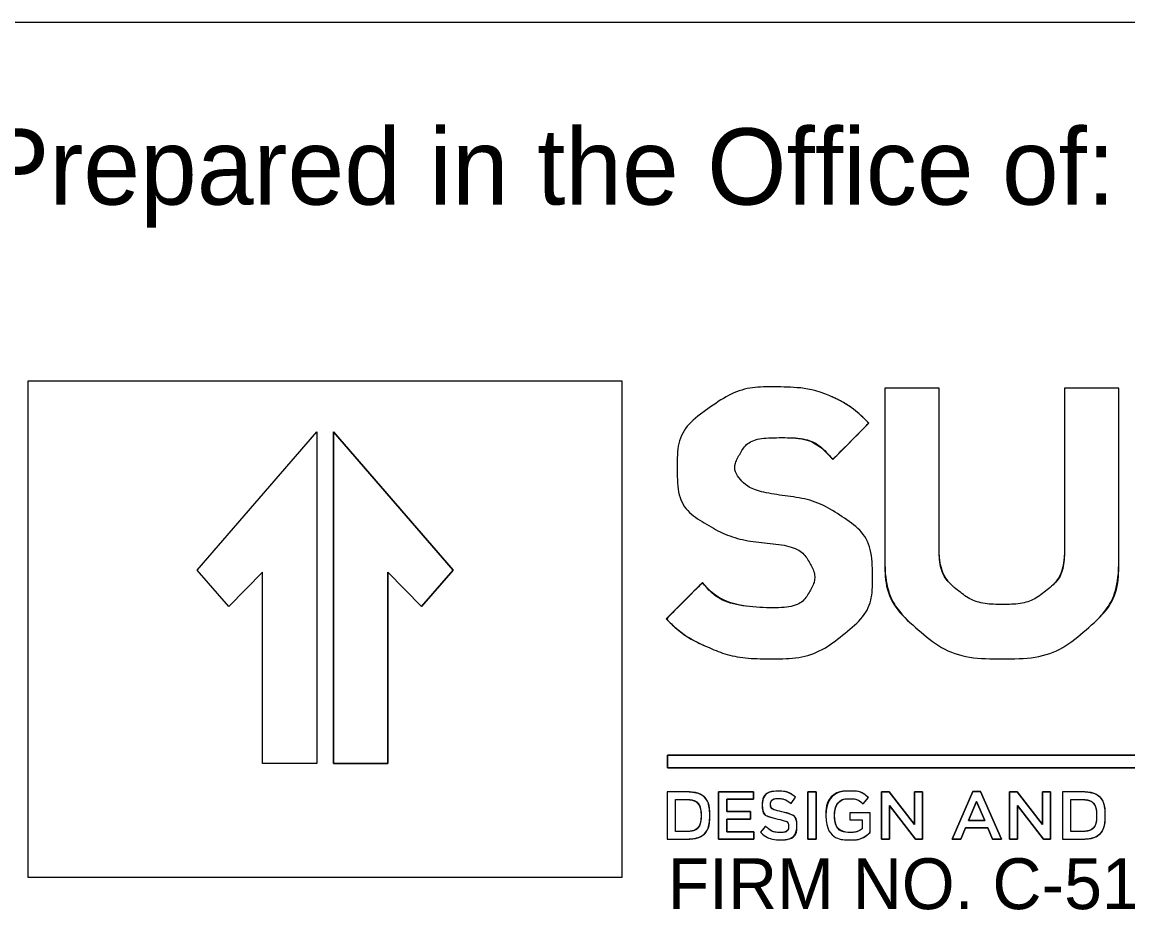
# Model space of a CAD drawing. Extents: x 1359317 to 1361345, y 1001522 to 1002524.
# Drawn here: x 1359513.4 to 1359573.9, y 1001664.8 to 1001713.3 of the extents above; entities that cross this region are included whole.
import ezdxf

# ---------------------------------------------------------------- set-up
doc = ezdxf.new("R2010")
doc.units = 0
doc.layers.add('Old_Level_3', color=7, linetype='Continuous')
doc.layers.add('Sheet Title CELL', color=7, linetype='Continuous')

msp = doc.modelspace()

# ---------------------------------------------------------------- linework, layer by layer
at = {"layer": 'Old_Level_3'}
for p, q in [((1359557.722, 1001689.42), (1359559.699, 1001691.4)), ((1359550.603, 1001682.684), (1359548.625, 1001680.703)), ((1359553.873, 1001670.535), (1359553.873, 1001670.527)), ((1359554.326, 1001670.568), (1359554.326, 1001670.575)), ((1359555.446, 1001670.616), (1359555.689, 1001670.959)), ((1359559.387, 1001670.598), (1359559.674, 1001670.941)), ((1359550.525, 1001669.955), (1359550.525, 1001669.948)), ((1359551.001, 1001669.955), (1359551.001, 1001669.963)), ((1359557.353, 1001669.955), (1359557.353, 1001669.948)), ((1359557.828, 1001669.955), (1359557.828, 1001669.963)), ((1359572.156, 1001669.955), (1359572.156, 1001669.948)), ((1359572.631, 1001669.955), (1359572.631, 1001669.963)), ((1359554.042, 1001669.365), (1359553.77, 1001669.04)), ((1359555.313, 1001669.361), (1359555.313, 1001669.354)), ((1359555.766, 1001669.398), (1359555.766, 1001669.406))]:
    msp.add_line(p, q, dxfattribs=at)
for points in [[(1359546.211, 1001693.693), (1359513.702, 1001693.693), (1359513.702, 1001666.583), (1359546.211, 1001666.583), (1359546.211, 1001693.693)], [(1359546.211, 1001693.693), (1359513.702, 1001693.693), (1359513.702, 1001666.583), (1359546.211, 1001666.583), (1359546.211, 1001693.693)], [(1359563.543, 1001684.765), (1359563.543, 1001693.322), (1359560.571, 1001693.322), (1359560.571, 1001683.972)], [(1359573.374, 1001683.972), (1359573.374, 1001693.322), (1359570.402, 1001693.322), (1359570.402, 1001684.765)], [(1359529.517, 1001690.92), (1359529.517, 1001672.793), (1359526.545, 1001672.793), (1359526.545, 1001683.249), (1359524.704, 1001681.377), (1359522.973, 1001683.363), (1359529.517, 1001690.92)], [(1359529.517, 1001690.92), (1359529.517, 1001672.793), (1359526.545, 1001672.793), (1359526.545, 1001683.249), (1359524.704, 1001681.377), (1359522.973, 1001683.363), (1359529.517, 1001690.92)], [(1359536.975, 1001683.363), (1359535.244, 1001681.377), (1359533.403, 1001683.249), (1359533.403, 1001672.793), (1359530.431, 1001672.793), (1359530.431, 1001690.92), (1359536.975, 1001683.363)], [(1359620.7, 1001672.564), (1359548.682, 1001672.564), (1359548.682, 1001673.251), (1359620.7, 1001673.251), (1359620.7, 1001672.564)], [(1359620.7, 1001673.251), (1359548.682, 1001673.251), (1359548.682, 1001672.564), (1359620.7, 1001672.564), (1359620.7, 1001673.251)], [(1359549.63, 1001671.247), (1359548.669, 1001671.247), (1359548.669, 1001668.664), (1359549.63, 1001668.664)], [(1359551.475, 1001671.247), (1359553.387, 1001671.247), (1359553.387, 1001670.841), (1359551.928, 1001670.841), (1359551.928, 1001670.169), (1359553.221, 1001670.169), (1359553.221, 1001669.763), (1359551.928, 1001669.763), (1359551.928, 1001669.07), (1359553.405, 1001669.07), (1359553.405, 1001668.664), (1359551.475, 1001668.664), (1359551.475, 1001671.247)], [(1359551.475, 1001668.664), (1359553.405, 1001668.664), (1359553.405, 1001669.07), (1359551.928, 1001669.07), (1359551.928, 1001669.763), (1359553.221, 1001669.763), (1359553.221, 1001670.169), (1359551.928, 1001670.169), (1359551.928, 1001670.841), (1359553.387, 1001670.841), (1359553.387, 1001671.247), (1359551.475, 1001671.247), (1359551.475, 1001668.664)], [(1359556.362, 1001671.247), (1359556.816, 1001671.247), (1359556.816, 1001668.664), (1359556.362, 1001668.664), (1359556.362, 1001671.247)], [(1359556.362, 1001668.664), (1359556.816, 1001668.664), (1359556.816, 1001671.247), (1359556.362, 1001671.247), (1359556.362, 1001668.664)], [(1359560.392, 1001671.247), (1359560.811, 1001671.247), (1359562.193, 1001669.461), (1359562.193, 1001671.247), (1359562.639, 1001671.247), (1359562.639, 1001668.664), (1359562.259, 1001668.664), (1359560.837, 1001670.502), (1359560.837, 1001668.664), (1359560.392, 1001668.664), (1359560.392, 1001671.247)], [(1359560.392, 1001668.664), (1359560.837, 1001668.664), (1359560.837, 1001670.502), (1359562.259, 1001668.664), (1359562.639, 1001668.664), (1359562.639, 1001671.247), (1359562.193, 1001671.247), (1359562.193, 1001669.461), (1359560.811, 1001671.247), (1359560.392, 1001671.247), (1359560.392, 1001668.664)], [(1359565.393, 1001671.265), (1359565.814, 1001671.265), (1359566.948, 1001668.664), (1359566.469, 1001668.664), (1359566.207, 1001669.287), (1359564.988, 1001669.287), (1359564.723, 1001668.664), (1359564.259, 1001668.664), (1359565.393, 1001671.265)], [(1359564.259, 1001668.664), (1359564.723, 1001668.664), (1359564.988, 1001669.287), (1359566.207, 1001669.287), (1359566.469, 1001668.664), (1359566.948, 1001668.664), (1359565.814, 1001671.265), (1359565.393, 1001671.265), (1359564.259, 1001668.664)], [(1359567.389, 1001671.247), (1359567.81, 1001671.247), (1359569.191, 1001669.461), (1359569.191, 1001671.247), (1359569.637, 1001671.247), (1359569.637, 1001668.664), (1359569.257, 1001668.664), (1359567.835, 1001670.502), (1359567.835, 1001668.664), (1359567.389, 1001668.664), (1359567.389, 1001671.247)], [(1359567.389, 1001668.664), (1359567.835, 1001668.664), (1359567.835, 1001670.502), (1359569.257, 1001668.664), (1359569.637, 1001668.664), (1359569.637, 1001671.247), (1359569.191, 1001671.247), (1359569.191, 1001669.461), (1359567.81, 1001671.247), (1359567.389, 1001671.247), (1359567.389, 1001668.664)], [(1359571.261, 1001671.247), (1359570.299, 1001671.247), (1359570.299, 1001668.664), (1359571.261, 1001668.664)], [(1359549.63, 1001669.077), (1359549.122, 1001669.077), (1359549.122, 1001670.834), (1359549.63, 1001670.834)], [(1359566.042, 1001669.69), (1359565.596, 1001670.723), (1359565.154, 1001669.69), (1359566.042, 1001669.69)], [(1359565.154, 1001669.69), (1359565.596, 1001670.723), (1359566.042, 1001669.69), (1359565.154, 1001669.69)], [(1359571.261, 1001669.077), (1359570.753, 1001669.077), (1359570.753, 1001670.834), (1359571.261, 1001670.834)], [(1359559.766, 1001669.022), (1359559.766, 1001670.107), (1359558.668, 1001670.107), (1359558.668, 1001669.712), (1359559.328, 1001669.712), (1359559.328, 1001669.228)]]:
    msp.add_lwpolyline(points, dxfattribs=at)
msp.add_lwpolyline([(1359530.431, 1001690.92), (1359530.431, 1001672.793), (1359533.403, 1001672.793), (1359533.403, 1001683.249), (1359535.244, 1001681.377), (1359536.975, 1001683.363)], close=True, dxfattribs=at)
for points, degree in [([(1359557.573, 1001692.886), (1359558.331, 1001692.557), (1359559.04, 1001692.061), (1359559.699, 1001691.4), (1359559.699, 1001691.4), (1359557.722, 1001689.42), (1359557.722, 1001689.42), (1359557.062, 1001690.212), (1359556.14, 1001690.609), (1359554.952, 1001690.609), (1359553.767, 1001690.609), (1359553.008, 1001690.328), (1359552.678, 1001689.766), (1359552.349, 1001689.205), (1359552.349, 1001688.727), (1359552.678, 1001688.331), (1359553.008, 1001687.934), (1359553.767, 1001687.637), (1359554.952, 1001687.439), (1359556.205, 1001687.307), (1359557.343, 1001686.894), (1359558.365, 1001686.201), (1359559.386, 1001685.508), (1359559.896, 1001684.402), (1359559.896, 1001682.883), (1359559.896, 1001681.693), (1359559.352, 1001680.67), (1359558.261, 1001679.812), (1359557.17, 1001678.954), (1359555.899, 1001678.524), (1359554.448, 1001678.524), (1359553.071, 1001678.524), (1359551.921, 1001678.722), (1359550.997, 1001679.118), (1359550.074, 1001679.515), (1359549.284, 1001680.043), (1359548.625, 1001680.703), (1359548.625, 1001680.703), (1359550.603, 1001682.684), (1359550.603, 1001682.684), (1359551.262, 1001681.892), (1359552.383, 1001681.43), (1359553.964, 1001681.298), (1359555.283, 1001681.298), (1359556.105, 1001681.579), (1359556.432, 1001682.14), (1359556.758, 1001682.701), (1359556.758, 1001683.262), (1359556.432, 1001683.824), (1359556.105, 1001684.385), (1359555.283, 1001684.731), (1359553.964, 1001684.863), (1359552.778, 1001684.995), (1359551.69, 1001685.359), (1359550.701, 1001685.953), (1359549.713, 1001686.548), (1359549.217, 1001687.571), (1359549.217, 1001689.024), (1359549.217, 1001690.337), (1359549.78, 1001691.392), (1359550.904, 1001692.188), (1359552.028, 1001692.985), (1359553.183, 1001693.382), (1359554.369, 1001693.382), (1359555.747, 1001693.382), (1359556.815, 1001693.218), (1359557.573, 1001692.886)], 3), ([(1359557.573, 1001692.886), (1359556.815, 1001693.218), (1359555.747, 1001693.382), (1359554.369, 1001693.382), (1359553.183, 1001693.382), (1359552.028, 1001692.985), (1359550.904, 1001692.188), (1359549.78, 1001691.392), (1359549.217, 1001690.337), (1359549.217, 1001689.024), (1359549.217, 1001687.571), (1359549.713, 1001686.548), (1359550.701, 1001685.953), (1359551.69, 1001685.359), (1359552.778, 1001684.995), (1359553.964, 1001684.863), (1359555.283, 1001684.731), (1359556.105, 1001684.385), (1359556.432, 1001683.824), (1359556.758, 1001683.262), (1359556.758, 1001682.701), (1359556.432, 1001682.14), (1359556.105, 1001681.579), (1359555.283, 1001681.298), (1359553.964, 1001681.298), (1359552.383, 1001681.43), (1359551.262, 1001681.892), (1359550.603, 1001682.684)], 3), ([(1359559.699, 1001691.4), (1359559.04, 1001692.061), (1359558.331, 1001692.557), (1359557.573, 1001692.886)], 2), ([(1359563.543, 1001693.322), (1359563.543, 1001693.322), (1359563.543, 1001684.765), (1359563.543, 1001684.765), (1359563.543, 1001683.642), (1359563.88, 1001682.817), (1359564.539, 1001682.288), (1359565.199, 1001681.76), (1359566.026, 1001681.496), (1359567.015, 1001681.496), (1359568.004, 1001681.496), (1359568.791, 1001681.76), (1359569.45, 1001682.288), (1359570.109, 1001682.817), (1359570.402, 1001683.642), (1359570.402, 1001684.765), (1359570.402, 1001684.765), (1359570.402, 1001693.322), (1359570.402, 1001693.322), (1359570.402, 1001693.322), (1359573.374, 1001693.322), (1359573.374, 1001693.322), (1359573.374, 1001693.322), (1359573.374, 1001683.972), (1359573.374, 1001683.972), (1359573.374, 1001682.453), (1359572.8, 1001681.166), (1359571.58, 1001680.109), (1359570.361, 1001679.053), (1359568.847, 1001678.524), (1359567.001, 1001678.524), (1359565.155, 1001678.524), (1359563.62, 1001679.053), (1359562.402, 1001680.109), (1359561.181, 1001681.166), (1359560.571, 1001682.453), (1359560.571, 1001683.972), (1359560.571, 1001683.972), (1359560.571, 1001693.322), (1359560.571, 1001693.322), (1359560.571, 1001693.322), (1359563.543, 1001693.322), (1359563.543, 1001693.322)], 3), ([(1359548.625, 1001680.703), (1359549.284, 1001680.043), (1359550.074, 1001679.515), (1359550.997, 1001679.118), (1359551.921, 1001678.722), (1359553.071, 1001678.524), (1359554.448, 1001678.524), (1359555.899, 1001678.524), (1359557.17, 1001678.954), (1359558.261, 1001679.812), (1359559.352, 1001680.67), (1359559.896, 1001681.693), (1359559.896, 1001682.883), (1359559.896, 1001684.402), (1359559.386, 1001685.508), (1359558.365, 1001686.201), (1359557.343, 1001686.894), (1359556.205, 1001687.307), (1359554.952, 1001687.439), (1359553.767, 1001687.637), (1359553.008, 1001687.934), (1359552.678, 1001688.331), (1359552.349, 1001688.727), (1359552.349, 1001689.205), (1359552.678, 1001689.766), (1359553.008, 1001690.328), (1359553.767, 1001690.609), (1359554.952, 1001690.609), (1359556.14, 1001690.609), (1359557.062, 1001690.212), (1359557.722, 1001689.42)], 3), ([(1359570.402, 1001684.765), (1359570.402, 1001683.642), (1359570.109, 1001682.817), (1359569.45, 1001682.288), (1359568.791, 1001681.76), (1359568.004, 1001681.496), (1359567.015, 1001681.496), (1359566.026, 1001681.496), (1359565.199, 1001681.76), (1359564.539, 1001682.288), (1359563.88, 1001682.817), (1359563.543, 1001683.642), (1359563.543, 1001684.765)], 3), ([(1359560.571, 1001683.972), (1359560.571, 1001682.453), (1359561.181, 1001681.166), (1359562.402, 1001680.109), (1359563.62, 1001679.053), (1359565.155, 1001678.524), (1359567.001, 1001678.524), (1359568.847, 1001678.524), (1359570.361, 1001679.053), (1359571.58, 1001680.109), (1359572.8, 1001681.166), (1359573.374, 1001682.453), (1359573.374, 1001683.972)], 3), ([(1359548.669, 1001671.247), (1359548.669, 1001671.247), (1359549.63, 1001671.247), (1359549.63, 1001671.247), (1359550.441, 1001671.247), (1359551.001, 1001670.69), (1359551.001, 1001669.963), (1359551.001, 1001669.963), (1359551.001, 1001669.955), (1359551.001, 1001669.955), (1359551.001, 1001669.228), (1359550.441, 1001668.664), (1359549.63, 1001668.664), (1359549.63, 1001668.664), (1359548.669, 1001668.664), (1359548.669, 1001668.664), (1359548.669, 1001668.664), (1359548.669, 1001671.247), (1359548.669, 1001671.247)], 3), ([(1359551.001, 1001669.963), (1359551.001, 1001670.69), (1359550.441, 1001671.247), (1359549.63, 1001671.247)], 2), ([(1359553.77, 1001669.04), (1359553.77, 1001669.04), (1359554.042, 1001669.365), (1359554.042, 1001669.365), (1359554.289, 1001669.151), (1359554.539, 1001669.029), (1359554.857, 1001669.029), (1359555.136, 1001669.029), (1359555.313, 1001669.162), (1359555.313, 1001669.354), (1359555.313, 1001669.354), (1359555.313, 1001669.361), (1359555.313, 1001669.361), (1359555.313, 1001669.546), (1359555.21, 1001669.645), (1359554.731, 1001669.756), (1359554.182, 1001669.889), (1359553.873, 1001670.051), (1359553.873, 1001670.527), (1359553.873, 1001670.527), (1359553.873, 1001670.535), (1359553.873, 1001670.535), (1359553.873, 1001670.978), (1359554.241, 1001671.284), (1359554.753, 1001671.284), (1359555.129, 1001671.284), (1359555.427, 1001671.17), (1359555.689, 1001670.959), (1359555.689, 1001670.959), (1359555.446, 1001670.616), (1359555.446, 1001670.616), (1359555.214, 1001670.789), (1359554.982, 1001670.882), (1359554.746, 1001670.882), (1359554.481, 1001670.882), (1359554.326, 1001670.745), (1359554.326, 1001670.575), (1359554.326, 1001670.575), (1359554.326, 1001670.568), (1359554.326, 1001670.568), (1359554.326, 1001670.369), (1359554.444, 1001670.28), (1359554.941, 1001670.162), (1359555.486, 1001670.029), (1359555.766, 1001669.834), (1359555.766, 1001669.406), (1359555.766, 1001669.406), (1359555.766, 1001669.398), (1359555.766, 1001669.398), (1359555.766, 1001668.915), (1359555.387, 1001668.627), (1359554.845, 1001668.627), (1359554.451, 1001668.627), (1359554.079, 1001668.763), (1359553.77, 1001669.04)], 3), ([(1359555.689, 1001670.959), (1359555.427, 1001671.17), (1359555.129, 1001671.284), (1359554.753, 1001671.284), (1359554.241, 1001671.284), (1359553.873, 1001670.978), (1359553.873, 1001670.535)], 3), ([(1359557.353, 1001669.948), (1359557.353, 1001669.948), (1359557.353, 1001669.955), (1359557.353, 1001669.955), (1359557.353, 1001670.679), (1359557.906, 1001671.291), (1359558.683, 1001671.291), (1359559.132, 1001671.291), (1359559.409, 1001671.166), (1359559.674, 1001670.941), (1359559.674, 1001670.941), (1359559.387, 1001670.598), (1359559.387, 1001670.598), (1359559.187, 1001670.767), (1359558.993, 1001670.874), (1359558.665, 1001670.874), (1359558.189, 1001670.874), (1359557.828, 1001670.457), (1359557.828, 1001669.963), (1359557.828, 1001669.963), (1359557.828, 1001669.955), (1359557.828, 1001669.955), (1359557.828, 1001669.424), (1359558.178, 1001669.033), (1359558.705, 1001669.033), (1359558.948, 1001669.033), (1359559.169, 1001669.11), (1359559.328, 1001669.228), (1359559.328, 1001669.228), (1359559.328, 1001669.712), (1359559.328, 1001669.712), (1359559.328, 1001669.712), (1359558.668, 1001669.712), (1359558.668, 1001669.712), (1359558.668, 1001669.712), (1359558.668, 1001670.107), (1359558.668, 1001670.107), (1359558.668, 1001670.107), (1359559.766, 1001670.107), (1359559.766, 1001670.107), (1359559.766, 1001670.107), (1359559.766, 1001669.022), (1359559.766, 1001669.022), (1359559.512, 1001668.804), (1359559.147, 1001668.619), (1359558.69, 1001668.619), (1359557.884, 1001668.619), (1359557.353, 1001669.195), (1359557.353, 1001669.948)], 3), ([(1359559.674, 1001670.941), (1359559.409, 1001671.166), (1359559.132, 1001671.291), (1359558.683, 1001671.291), (1359557.906, 1001671.291), (1359557.353, 1001670.679), (1359557.353, 1001669.955)], 3), ([(1359570.299, 1001671.247), (1359570.299, 1001671.247), (1359571.261, 1001671.247), (1359571.261, 1001671.247), (1359572.071, 1001671.247), (1359572.631, 1001670.69), (1359572.631, 1001669.963), (1359572.631, 1001669.963), (1359572.631, 1001669.955), (1359572.631, 1001669.955), (1359572.631, 1001669.228), (1359572.071, 1001668.664), (1359571.261, 1001668.664), (1359571.261, 1001668.664), (1359570.299, 1001668.664), (1359570.299, 1001668.664), (1359570.299, 1001668.664), (1359570.299, 1001671.247), (1359570.299, 1001671.247)], 3), ([(1359572.631, 1001669.963), (1359572.631, 1001670.69), (1359572.071, 1001671.247), (1359571.261, 1001671.247)], 2), ([(1359549.122, 1001670.834), (1359549.122, 1001670.834), (1359549.122, 1001669.077), (1359549.122, 1001669.077), (1359549.122, 1001669.077), (1359549.63, 1001669.077), (1359549.63, 1001669.077), (1359550.172, 1001669.077), (1359550.525, 1001669.442), (1359550.525, 1001669.948), (1359550.525, 1001669.948), (1359550.525, 1001669.955), (1359550.525, 1001669.955), (1359550.525, 1001670.461), (1359550.172, 1001670.834), (1359549.63, 1001670.834), (1359549.63, 1001670.834), (1359549.122, 1001670.834), (1359549.122, 1001670.834)], 3), ([(1359549.63, 1001670.834), (1359550.172, 1001670.834), (1359550.525, 1001670.461), (1359550.525, 1001669.955)], 2), ([(1359553.873, 1001670.527), (1359553.873, 1001670.051), (1359554.182, 1001669.889), (1359554.731, 1001669.756), (1359555.21, 1001669.645), (1359555.313, 1001669.546), (1359555.313, 1001669.361)], 3), ([(1359554.326, 1001670.575), (1359554.326, 1001670.745), (1359554.481, 1001670.882), (1359554.746, 1001670.882), (1359554.982, 1001670.882), (1359555.214, 1001670.789), (1359555.446, 1001670.616)], 3), ([(1359555.766, 1001669.406), (1359555.766, 1001669.834), (1359555.486, 1001670.029), (1359554.941, 1001670.162), (1359554.444, 1001670.28), (1359554.326, 1001670.369), (1359554.326, 1001670.568)], 3), ([(1359557.828, 1001669.963), (1359557.828, 1001670.457), (1359558.189, 1001670.874), (1359558.665, 1001670.874), (1359558.993, 1001670.874), (1359559.187, 1001670.767), (1359559.387, 1001670.598)], 3), ([(1359570.753, 1001670.834), (1359570.753, 1001670.834), (1359570.753, 1001669.077), (1359570.753, 1001669.077), (1359570.753, 1001669.077), (1359571.261, 1001669.077), (1359571.261, 1001669.077), (1359571.802, 1001669.077), (1359572.156, 1001669.442), (1359572.156, 1001669.948), (1359572.156, 1001669.948), (1359572.156, 1001669.955), (1359572.156, 1001669.955), (1359572.156, 1001670.461), (1359571.802, 1001670.834), (1359571.261, 1001670.834), (1359571.261, 1001670.834), (1359570.753, 1001670.834), (1359570.753, 1001670.834)], 3), ([(1359571.261, 1001670.834), (1359571.802, 1001670.834), (1359572.156, 1001670.461), (1359572.156, 1001669.955)], 2), ([(1359549.63, 1001668.664), (1359550.441, 1001668.664), (1359551.001, 1001669.228), (1359551.001, 1001669.955)], 2), ([(1359550.525, 1001669.948), (1359550.525, 1001669.442), (1359550.172, 1001669.077), (1359549.63, 1001669.077)], 2), ([(1359557.353, 1001669.948), (1359557.353, 1001669.195), (1359557.884, 1001668.619), (1359558.69, 1001668.619), (1359559.147, 1001668.619), (1359559.512, 1001668.804), (1359559.766, 1001669.022)], 3), ([(1359559.328, 1001669.228), (1359559.169, 1001669.11), (1359558.948, 1001669.033), (1359558.705, 1001669.033), (1359558.178, 1001669.033), (1359557.828, 1001669.424), (1359557.828, 1001669.955)], 3), ([(1359571.261, 1001668.664), (1359572.071, 1001668.664), (1359572.631, 1001669.228), (1359572.631, 1001669.955)], 2), ([(1359572.156, 1001669.948), (1359572.156, 1001669.442), (1359571.802, 1001669.077), (1359571.261, 1001669.077)], 2), ([(1359553.77, 1001669.04), (1359554.079, 1001668.763), (1359554.451, 1001668.627), (1359554.845, 1001668.627), (1359555.387, 1001668.627), (1359555.766, 1001668.915), (1359555.766, 1001669.398)], 3), ([(1359555.313, 1001669.354), (1359555.313, 1001669.162), (1359555.136, 1001669.029), (1359554.857, 1001669.029), (1359554.539, 1001669.029), (1359554.289, 1001669.151), (1359554.042, 1001669.365)], 3)]:
    msp.add_open_spline(points, degree=degree, dxfattribs=at)
at = {"layer": 'Sheet Title CELL'}
msp.add_line((1359507.258, 1001713.321), (1359804.975, 1001713.321), dxfattribs=at)

# ---------------------------------------------------------------- texts
at = {"layer": 'Old_Level_3'}
msp.add_text('FIRM NO. C-5176', height=2.78018, rotation=360, dxfattribs=at).set_placement((1359548.697, 1001664.838))
at = {"layer": 'Sheet Title CELL'}
msp.add_text('Prepared in the Office of:', height=4.17141, rotation=360, dxfattribs=at).set_placement((1359511.166, 1001703.346))

doc.saveas('drawing.dxf')
